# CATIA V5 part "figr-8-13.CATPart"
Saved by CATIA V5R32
Part number: Part1
Bounding box of the stored display mesh (mm): x 4.549 to 89.781, y -52.238 to 26.36, z 54 to 147.773
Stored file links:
  D:\PROJECTS\Project 2022\CATIA V5 6R 2022\Resources\Part Files\c08_catia_v5_6r2022_prt\figr-8-13.CATPart
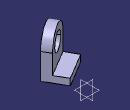
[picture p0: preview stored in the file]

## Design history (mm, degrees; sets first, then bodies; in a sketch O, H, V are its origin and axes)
Body1 (main body)
  Sketch1 on yz-plane, origin (0, 0, 0), H (0, 1, 0), V (0, 0, 1)
    point P1 (-104.4861, 0)
    line L1 (-104.4861, 0) -> (-104.4861, 44.267)
    arc A1 centre (-69.7903, 44.267) radius 34.6958 from (-104.4861, 44.267) to (-35.0946, 44.267) cw
    line L2 (-35.0946, 44.267) -> (-35.0946, 0)
    point P5 (-35.0946, 0)
    line L3 (-35.0946, 0) -> (-104.4861, 0)
    circle A2 centre (-69.7903, 44.267) radius 19.5413
    coincidence: P1 H, P5 H
    vertical: L1 V
    tangency: A1 L1, L2 A1
    horizontal: L3 H
  Pad1: profile Sketch1, direction (1, 0, 0), length 20
  Sketch2 on face of Pad1, origin (0, 0, 0), H (0, -1, 0), V (0, 0, 1)
    point P1 (35.0946, 0)
    line L1 (35.0946, 0) -> (104.4861, 0)
    line L2 (104.4861, 0) -> (104.4861, -15)
    line L3 (104.4861, -15) -> (35.0946, -15)
    line L4 (35.0946, -15) -> (35.0946, 0)
    reference projected line E1 (35.0946, 0) -> (35.0946, 44.267) from edge [face of Pad1 | face of Pad1]
    reference projected line E2 (104.4861, 44.267) -> (104.4861, 0) from edge [face of Pad1 | face of Pad1]
    distance L3 L1 = 15
    coincidence: P1 H, L4 E1, L2 E2
    horizontal: L1 H, L3 H
    vertical: L2 V, L4 V
  Pad2: profile Sketch2, direction (1, 0, 0), length 50
  Translate1: Direction xy-plane, ToTransfor Pad2, Length 69
  Rotate1: Axis edge, ToTransfor Translate1, Angle 121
